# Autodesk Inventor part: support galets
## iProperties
Shininess: 64.0
Length Units: 11269
Angle Units: 11279
Time Units: 11290
Mass Units: 11283
Length Display Precision: 3
Angle Display Precision: 2
Compacted: True
Part Number: support galets
Document SubType Name: Modeling
Created: 2005-02
Material: Par défaut
Designer: LEGERET Philippe
Density: 0.0
Volumn: 0.0
Area: 0.0
PropertySet Name: Model Information
Control State: 0
Master: False
Checked Out: False
Author: LEGERET Philippe
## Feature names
1. Extrusion1
2. Chanfrein1 [Chamfer]
3. Chanfrein2 [Chamfer]
4. Perçage1 [Hole]
5. Perçage2 [Hole]
6. Extrusion2
